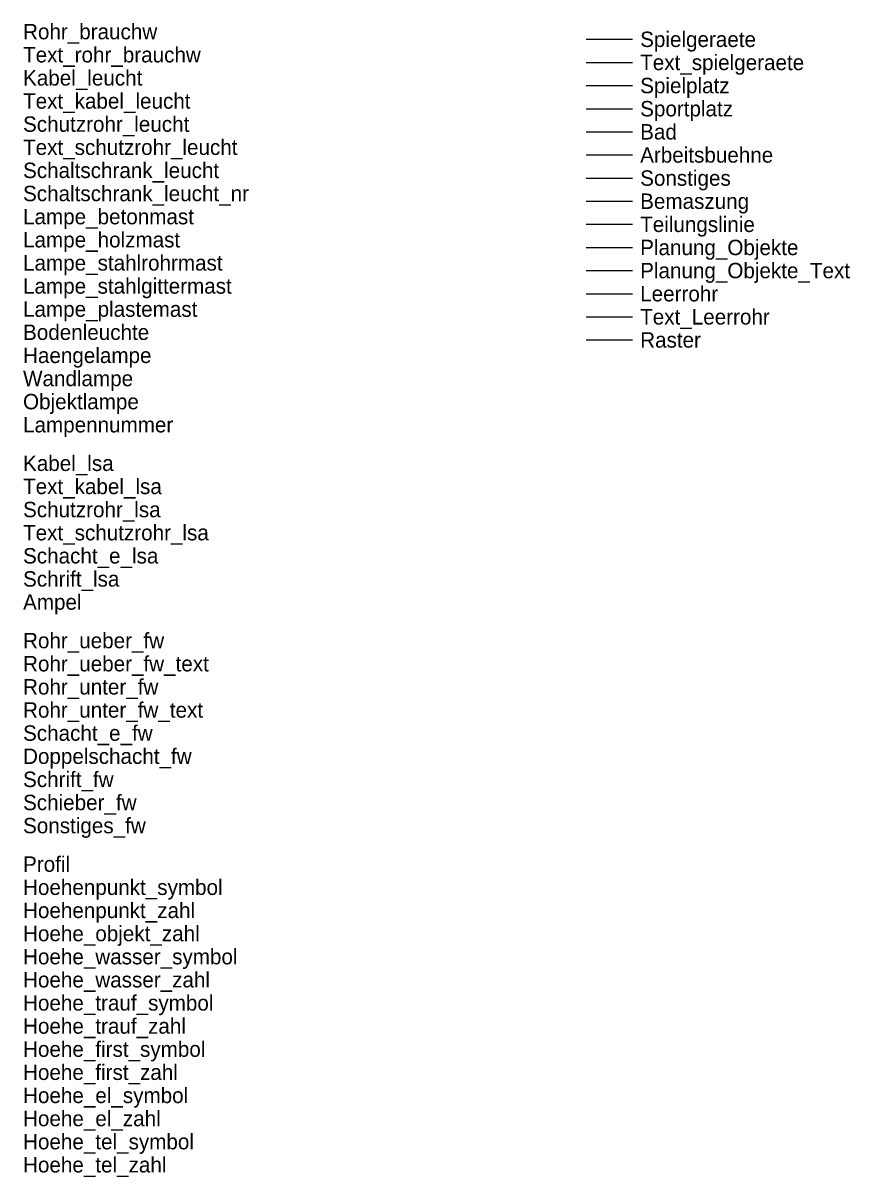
# Model space of a CAD drawing. Extents: x 0 to 177, y -135 to 1.
# Drawn here: x 123.5 to 177.1, y -133.8 to -58.9 of the extents above; entities that cross this region are included whole.
import ezdxf

# ---------------------------------------------------------------- set-up
doc = ezdxf.new("R2010")
doc.units = 0
for name, color, linetype in [('Ampel', 7, 'Continuous'), ('Arbeitsbuehne', 7, 'Continuous'), ('Bad', 7, 'Continuous'), ('Bemaszung', 7, 'Continuous'), ('Bodenleuchte', 7, 'Continuous'), ('Doppelschacht_fw', 7, 'Continuous'), ('Haengelampe', 7, 'Continuous'), ('Hoehe_el_symbol', 7, 'Continuous'), ('Hoehe_el_zahl', 7, 'Continuous'), ('Hoehe_first_symbol', 7, 'Continuous'), ('Hoehe_first_zahl', 7, 'Continuous'), ('Hoehe_objekt_zahl', 7, 'Continuous'), ('Hoehe_tel_symbol', 7, 'Continuous'), ('Hoehe_tel_zahl', 7, 'Continuous'), ('Hoehe_trauf_symbol', 7, 'Continuous'), ('Hoehe_trauf_zahl', 7, 'Continuous'), ('Hoehe_wasser_symbol', 7, 'Continuous'), ('Hoehe_wasser_zahl', 7, 'Continuous'), ('Hoehenpunkt_symbol', 7, 'Continuous'), ('Hoehenpunkt_zahl', 7, 'Continuous'), ('Kabel_leucht', 7, 'Continuous'), ('Kabel_lsa', 7, 'Continuous'), ('Lampe_betonmast', 7, 'Continuous'), ('Lampe_holzmast', 7, 'Continuous'), ('Lampe_plastemast', 7, 'Continuous'), ('Lampe_stahlgittermast', 7, 'Continuous'), ('Lampe_stahlrohrmast', 7, 'Continuous'), ('Lampennummer', 7, 'Continuous'), ('Leerrohr', 7, 'Continuous'), ('Objektlampe', 7, 'Continuous'), ('Planung_Objekte', 7, 'Continuous'), ('Planung_Objekte_Text', 7, 'Continuous'), ('Profil', 7, 'Continuous'), ('Raster', 7, 'Continuous'), ('Rohr_brauchw', 7, 'Continuous'), ('Rohr_ueber_fw', 7, 'Continuous'), ('Rohr_ueber_fw_text', 7, 'Continuous'), ('Rohr_unter_fw', 7, 'Continuous'), ('Rohr_unter_fw_text', 7, 'Continuous'), ('Schacht_e_fw', 7, 'Continuous'), ('Schacht_e_lsa', 7, 'Continuous'), ('Schaltschrank_leucht', 7, 'Continuous'), ('Schaltschrank_leucht_nr', 7, 'Continuous'), ('Schieber_fw', 7, 'Continuous'), ('Schrift_fw', 7, 'Continuous'), ('Schrift_lsa', 7, 'Continuous'), ('Schutzrohr_leucht', 7, 'Continuous'), ('Schutzrohr_lsa', 7, 'Continuous'), ('Sonstiges', 7, 'Continuous'), ('Sonstiges_fw', 7, 'Continuous'), ('Spielgeraete', 7, 'Continuous'), ('Spielplatz', 7, 'Continuous'), ('Sportplatz', 7, 'Continuous'), ('Teilungslinie', 7, 'Continuous'), ('Text_kabel_leucht', 7, 'Continuous'), ('Text_kabel_lsa', 7, 'Continuous'), ('Text_Leerrohr', 7, 'Continuous'), ('Text_rohr_brauchw', 7, 'Continuous'), ('Text_schutzrohr_leucht', 7, 'Continuous'), ('Text_schutzrohr_lsa', 7, 'Continuous'), ('Text_spielgeraete', 7, 'Continuous'), ('Wandlampe', 7, 'Continuous')]:
    doc.layers.add(name, color=color, linetype=linetype)

msp = doc.modelspace()

# ---------------------------------------------------------------- linework, layer by layer
at = {"layer": 'Arbeitsbuehne'}
msp.add_line((160, -67.5), (163, -67.5), dxfattribs=at)
at = {"layer": 'Bad'}
msp.add_line((160, -66), (163, -66), dxfattribs=at)
at = {"layer": 'Bemaszung'}
msp.add_line((160, -70.5), (163, -70.5), dxfattribs=at)
at = {"layer": 'Leerrohr'}
msp.add_line((160, -76.5), (163, -76.5), dxfattribs=at)
at = {"layer": 'Planung_Objekte'}
msp.add_line((160, -73.5), (163, -73.5), dxfattribs=at)
at = {"layer": 'Planung_Objekte_Text'}
msp.add_line((160, -75), (163, -75), dxfattribs=at)
at = {"layer": 'Raster'}
msp.add_line((160, -79.5), (163, -79.5), dxfattribs=at)
at = {"layer": 'Sonstiges'}
msp.add_line((160, -69), (163, -69), dxfattribs=at)
at = {"layer": 'Spielgeraete'}
msp.add_line((160, -60), (163, -60), dxfattribs=at)
at = {"layer": 'Spielplatz'}
msp.add_line((160, -63), (163, -63), dxfattribs=at)
at = {"layer": 'Sportplatz'}
msp.add_line((160, -64.5), (163, -64.5), dxfattribs=at)
at = {"layer": 'Teilungslinie'}
msp.add_line((160, -72), (163, -72), dxfattribs=at)
at = {"layer": 'Text_Leerrohr'}
msp.add_line((160, -78), (163, -78), dxfattribs=at)
at = {"layer": 'Text_spielgeraete'}
msp.add_line((160, -61.5), (163, -61.5), dxfattribs=at)

# ---------------------------------------------------------------- texts
at = {"layer": 'Ampel'}
msp.add_text('Ampel', height=1, dxfattribs=at).set_placement((123.5, -97))
at = {"layer": 'Arbeitsbuehne'}
msp.add_text('Arbeitsbuehne', height=1, dxfattribs=at).set_placement((163.5, -68))
at = {"layer": 'Bad'}
msp.add_text('Bad', height=1, dxfattribs=at).set_placement((163.5, -66.5))
at = {"layer": 'Bemaszung'}
msp.add_text('Bemaszung', height=1, dxfattribs=at).set_placement((163.5, -71))
at = {"layer": 'Bodenleuchte'}
msp.add_text('Bodenleuchte', height=1, dxfattribs=at).set_placement((123.5, -79.5))
at = {"layer": 'Doppelschacht_fw'}
msp.add_text('Doppelschacht_fw', height=1, dxfattribs=at).set_placement((123.5, -107))
at = {"layer": 'Haengelampe'}
msp.add_text('Haengelampe', height=1, dxfattribs=at).set_placement((123.5, -81))
at = {"layer": 'Hoehe_el_symbol'}
msp.add_text('Hoehe_el_symbol', height=1, dxfattribs=at).set_placement((123.5, -129))
at = {"layer": 'Hoehe_el_zahl'}
msp.add_text('Hoehe_el_zahl', height=1, dxfattribs=at).set_placement((123.5, -130.5))
at = {"layer": 'Hoehe_first_symbol'}
msp.add_text('Hoehe_first_symbol', height=1, dxfattribs=at).set_placement((123.5, -126))
at = {"layer": 'Hoehe_first_zahl'}
msp.add_text('Hoehe_first_zahl', height=1, dxfattribs=at).set_placement((123.5, -127.5))
at = {"layer": 'Hoehe_objekt_zahl'}
msp.add_text('Hoehe_objekt_zahl', height=1, dxfattribs=at).set_placement((123.5, -118.5))
at = {"layer": 'Hoehe_tel_symbol'}
msp.add_text('Hoehe_tel_symbol', height=1, dxfattribs=at).set_placement((123.5, -132))
at = {"layer": 'Hoehe_tel_zahl'}
msp.add_text('Hoehe_tel_zahl', height=1, dxfattribs=at).set_placement((123.5, -133.5))
at = {"layer": 'Hoehe_trauf_symbol'}
msp.add_text('Hoehe_trauf_symbol', height=1, dxfattribs=at).set_placement((123.5, -123))
at = {"layer": 'Hoehe_trauf_zahl'}
msp.add_text('Hoehe_trauf_zahl', height=1, dxfattribs=at).set_placement((123.5, -124.5))
at = {"layer": 'Hoehe_wasser_symbol'}
msp.add_text('Hoehe_wasser_symbol', height=1, dxfattribs=at).set_placement((123.5, -120))
at = {"layer": 'Hoehe_wasser_zahl'}
msp.add_text('Hoehe_wasser_zahl', height=1, dxfattribs=at).set_placement((123.5, -121.5))
at = {"layer": 'Hoehenpunkt_symbol'}
msp.add_text('Hoehenpunkt_symbol', height=1, dxfattribs=at).set_placement((123.5, -115.5))
at = {"layer": 'Hoehenpunkt_zahl'}
msp.add_text('Hoehenpunkt_zahl', height=1, dxfattribs=at).set_placement((123.5, -117))
at = {"layer": 'Kabel_leucht'}
msp.add_text('Kabel_leucht', height=1, dxfattribs=at).set_placement((123.5, -63))
at = {"layer": 'Kabel_lsa'}
msp.add_text('Kabel_lsa', height=1, dxfattribs=at).set_placement((123.5, -88))
at = {"layer": 'Lampe_betonmast'}
msp.add_text('Lampe_betonmast', height=1, dxfattribs=at).set_placement((123.5, -72))
at = {"layer": 'Lampe_holzmast'}
msp.add_text('Lampe_holzmast', height=1, dxfattribs=at).set_placement((123.5, -73.5))
at = {"layer": 'Lampe_plastemast'}
msp.add_text('Lampe_plastemast', height=1, dxfattribs=at).set_placement((123.5, -78))
at = {"layer": 'Lampe_stahlgittermast'}
msp.add_text('Lampe_stahlgittermast', height=1, dxfattribs=at).set_placement((123.5, -76.5))
at = {"layer": 'Lampe_stahlrohrmast'}
msp.add_text('Lampe_stahlrohrmast', height=1, dxfattribs=at).set_placement((123.5, -75))
at = {"layer": 'Lampennummer'}
msp.add_text('Lampennummer', height=1, dxfattribs=at).set_placement((123.5, -85.5))
at = {"layer": 'Leerrohr'}
msp.add_text('Leerrohr', height=1, dxfattribs=at).set_placement((163.5, -77))
at = {"layer": 'Objektlampe'}
msp.add_text('Objektlampe', height=1, dxfattribs=at).set_placement((123.5, -84))
at = {"layer": 'Planung_Objekte'}
msp.add_text('Planung_Objekte', height=1, dxfattribs=at).set_placement((163.5, -74))
at = {"layer": 'Planung_Objekte_Text'}
msp.add_text('Planung_Objekte_Text', height=1, dxfattribs=at).set_placement((163.5, -75.5))
at = {"layer": 'Profil'}
msp.add_text('Profil', height=1, dxfattribs=at).set_placement((123.5, -114))
at = {"layer": 'Raster'}
msp.add_text('Raster', height=1, dxfattribs=at).set_placement((163.5, -80))
at = {"layer": 'Rohr_brauchw'}
msp.add_text('Rohr_brauchw', height=1, dxfattribs=at).set_placement((123.5, -60))
at = {"layer": 'Rohr_ueber_fw'}
msp.add_text('Rohr_ueber_fw', height=1, dxfattribs=at).set_placement((123.5, -99.5))
at = {"layer": 'Rohr_ueber_fw_text'}
msp.add_text('Rohr_ueber_fw_text', height=1, dxfattribs=at).set_placement((123.5, -101))
at = {"layer": 'Rohr_unter_fw'}
msp.add_text('Rohr_unter_fw', height=1, dxfattribs=at).set_placement((123.5, -102.5))
at = {"layer": 'Rohr_unter_fw_text'}
msp.add_text('Rohr_unter_fw_text', height=1, dxfattribs=at).set_placement((123.5, -104))
at = {"layer": 'Schacht_e_fw'}
msp.add_text('Schacht_e_fw', height=1, dxfattribs=at).set_placement((123.5, -105.5))
at = {"layer": 'Schacht_e_lsa'}
msp.add_text('Schacht_e_lsa', height=1, dxfattribs=at).set_placement((123.5, -94))
at = {"layer": 'Schaltschrank_leucht'}
msp.add_text('Schaltschrank_leucht', height=1, dxfattribs=at).set_placement((123.5, -69))
at = {"layer": 'Schaltschrank_leucht_nr'}
msp.add_text('Schaltschrank_leucht_nr', height=1, dxfattribs=at).set_placement((123.5, -70.5))
at = {"layer": 'Schieber_fw'}
msp.add_text('Schieber_fw', height=1, dxfattribs=at).set_placement((123.5, -110))
at = {"layer": 'Schrift_fw'}
msp.add_text('Schrift_fw', height=1, dxfattribs=at).set_placement((123.5, -108.5))
at = {"layer": 'Schrift_lsa'}
msp.add_text('Schrift_lsa', height=1, dxfattribs=at).set_placement((123.5, -95.5))
at = {"layer": 'Schutzrohr_leucht'}
msp.add_text('Schutzrohr_leucht', height=1, dxfattribs=at).set_placement((123.5, -66))
at = {"layer": 'Schutzrohr_lsa'}
msp.add_text('Schutzrohr_lsa', height=1, dxfattribs=at).set_placement((123.5, -91))
at = {"layer": 'Sonstiges'}
msp.add_text('Sonstiges', height=1, dxfattribs=at).set_placement((163.5, -69.5))
at = {"layer": 'Sonstiges_fw'}
msp.add_text('Sonstiges_fw', height=1, dxfattribs=at).set_placement((123.5, -111.5))
at = {"layer": 'Spielgeraete'}
msp.add_text('Spielgeraete', height=1, dxfattribs=at).set_placement((163.5, -60.5))
at = {"layer": 'Spielplatz'}
msp.add_text('Spielplatz', height=1, dxfattribs=at).set_placement((163.5, -63.5))
at = {"layer": 'Sportplatz'}
msp.add_text('Sportplatz', height=1, dxfattribs=at).set_placement((163.5, -65))
at = {"layer": 'Teilungslinie'}
msp.add_text('Teilungslinie', height=1, dxfattribs=at).set_placement((163.5, -72.5))
at = {"layer": 'Text_kabel_leucht'}
msp.add_text('Text_kabel_leucht', height=1, dxfattribs=at).set_placement((123.5, -64.5))
at = {"layer": 'Text_kabel_lsa'}
msp.add_text('Text_kabel_lsa', height=1, dxfattribs=at).set_placement((123.5, -89.5))
at = {"layer": 'Text_Leerrohr'}
msp.add_text('Text_Leerrohr', height=1, dxfattribs=at).set_placement((163.5, -78.5))
at = {"layer": 'Text_rohr_brauchw'}
msp.add_text('Text_rohr_brauchw', height=1, dxfattribs=at).set_placement((123.5, -61.5))
at = {"layer": 'Text_schutzrohr_leucht'}
msp.add_text('Text_schutzrohr_leucht', height=1, dxfattribs=at).set_placement((123.5, -67.5))
at = {"layer": 'Text_schutzrohr_lsa'}
msp.add_text('Text_schutzrohr_lsa', height=1, dxfattribs=at).set_placement((123.5, -92.5))
at = {"layer": 'Text_spielgeraete'}
msp.add_text('Text_spielgeraete', height=1, dxfattribs=at).set_placement((163.5, -62))
at = {"layer": 'Wandlampe'}
msp.add_text('Wandlampe', height=1, dxfattribs=at).set_placement((123.5, -82.5))

doc.saveas('drawing.dxf')
